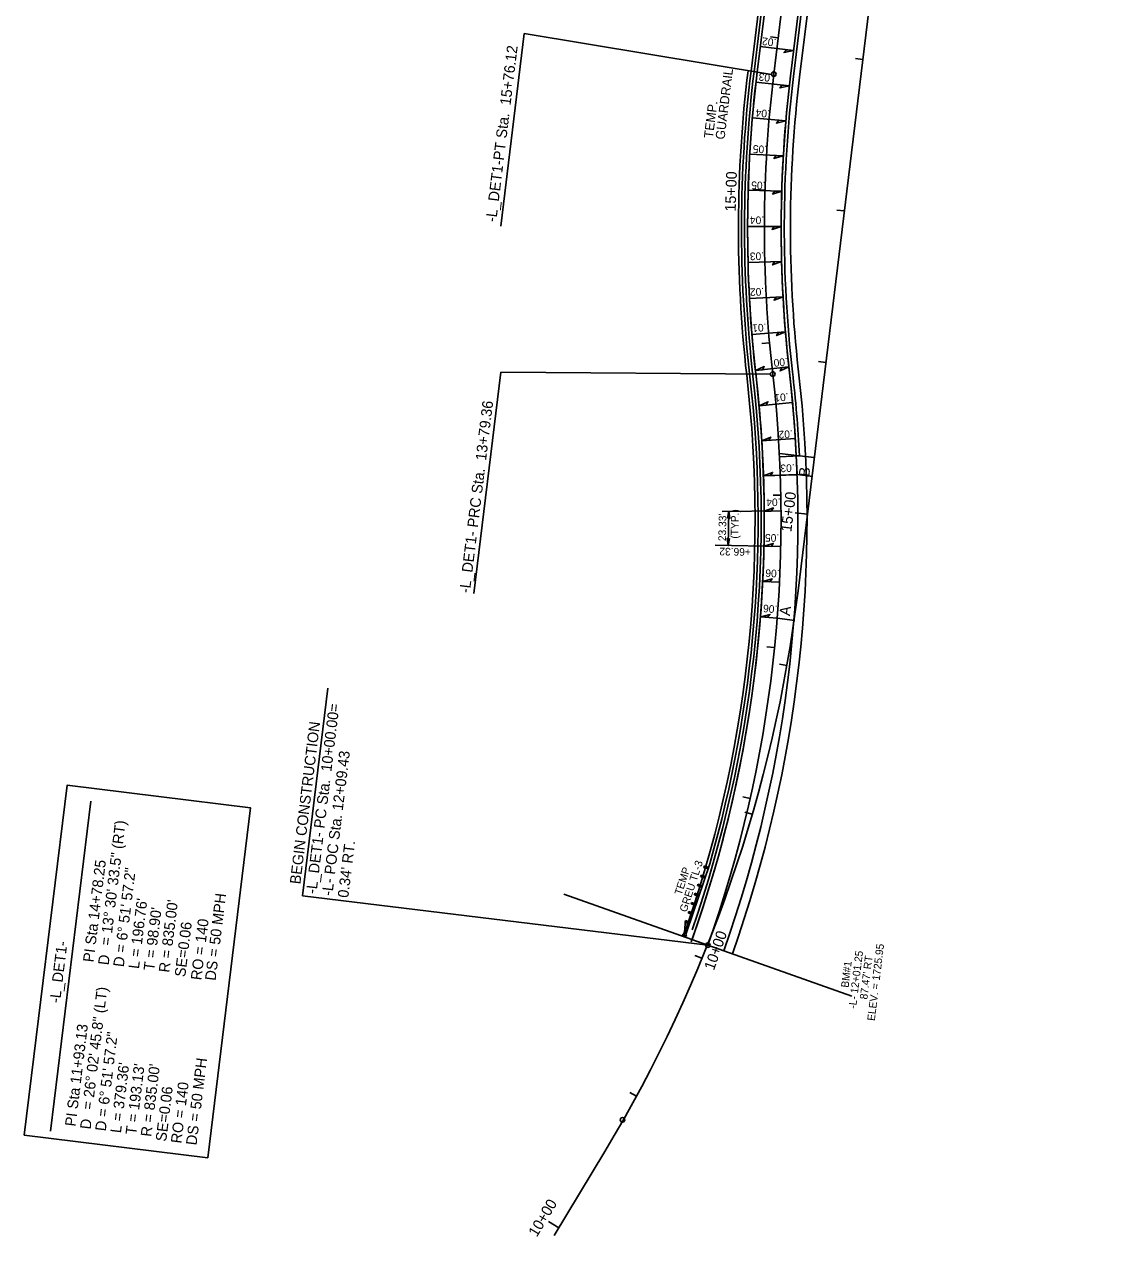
# Model space of a CAD drawing. Extents: x 473658 to 481584, y 489119 to 506230.
# Drawn here: x 480694 to 481402, y 489119 to 489912 of the extents above; entities that cross this region are included whole.
import ezdxf

# ---------------------------------------------------------------- set-up
doc = ezdxf.new("R2010")
doc.units = 0
for name, color, linetype in [('Default', 7, 'Continuous'), ('Exist Structure Minor Culvert Topo', 7, 'Continuous'), ('Prop EOT', 7, 'Continuous'), ('Prop Grid Mask', 7, 'Continuous'), ('Prop Guardrail', 7, 'Continuous'), ('Prop Guardrail Anchor Unit CELL', 7, 'Continuous'), ('Prop Horizontal Alignment', 7, 'Continuous'), ('Prop Horizontal Alignment Curve and Spiral Data', 7, 'Continuous'), ('Prop Horizontal Alignment Station Label', 7, 'Continuous'), ('Prop Horizontal Alignment Tick Label', 7, 'Continuous'), ('Prop Horizontal Alignment Tick Large', 7, 'Continuous'), ('Prop Horizontal Alignment Tick Small', 7, 'Continuous'), ('Prop Paved Shoulder', 7, 'Continuous'), ('Prop Superelevation  Arrow CELL', 7, 'Continuous'), ('Prop Superelevation Label', 7, 'Continuous'), ('Scratch_Level_2', 7, 'Continuous'), ('Scratch_Level_3', 7, 'Continuous'), ('Scratch_Level_4', 7, 'Continuous'), ('Scratch_Level_5', 7, 'Continuous'), ('Scratch_Level_6', 7, 'Continuous'), ('Scratch_Level_9', 7, 'Continuous'), ('Sheet Profile Grid Major CELL', 7, 'Continuous')]:
    doc.layers.add(name, color=color, linetype=linetype)

msp = doc.modelspace()

# ---------------------------------------------------------------- linework, layer by layer
at = {"layer": 'Prop EOT'}
for p, q in [((481195.32, 489878.54), (481333.26, 491007.97)), ((481173.48, 489881.21), (481217.26, 490239.65))]:
    msp.add_line(p, q, dxfattribs=at)
for centre, radius, start, end in [((482013.24, 489778.65), 846, 173.03651, 186.54581), ((482013.24, 489778.65), 824, 173.03651, 186.54581), ((480354.13, 489588.27), 824, 340.39021, 6.54581), ((480354.13, 489588.27), 846, 1.98866, 6.54581)]:
    msp.add_arc(centre, radius, start, end, dxfattribs=at)
at = {"layer": 'Prop Grid Mask'}
msp.add_lwpolyline([(480693.88, 489185.04), (480721.87, 489414.21), (480841.92, 489399.55), (480813.93, 489170.38)], close=True, dxfattribs=at)
at = {"layer": 'Prop Guardrail'}
msp.add_line((481207.7, 490194.38), (481169.51, 489881.7), dxfattribs=at)
for centre, radius, start, end in [((482013.24, 489778.65), 850, 173.03651, 186.54581), ((480354.13, 489588.27), 820, 344.04145, 6.54581)]:
    msp.add_arc(centre, radius, start, end, dxfattribs=at)
at = {"layer": 'Prop Guardrail Anchor Unit CELL'}
for p, q in [((481142.53, 489362.82), (481127.46, 489318.56)), ((481136.79, 489355.43), (481136.46, 489354.48)), ((481136.46, 489354.48), (481138.23, 489354.94)), ((481139.35, 489353.5), (481136.46, 489354.48)), ((481139.68, 489354.44), (481136.79, 489355.43)), ((481137.91, 489353.99), (481136.79, 489355.43)), ((481138.23, 489354.94), (481137.91, 489353.99)), ((481138.23, 489354.94), (481139.35, 489353.5)), ((481138.87, 489361.38), (481138.54, 489360.43)), ((481138.54, 489360.43), (481140.29, 489360.89)), ((481141.38, 489359.46), (481138.54, 489360.43)), ((481141.71, 489360.41), (481138.87, 489361.38)), ((481139.96, 489359.95), (481138.87, 489361.38)), ((481140.29, 489360.89), (481139.96, 489359.95)), ((481139.96, 489359.95), (481141.71, 489360.41)), ((481141.38, 489359.46), (481139.96, 489359.95)), ((481140.29, 489360.89), (481141.38, 489359.46)), ((481141.71, 489360.41), (481141.38, 489359.46)), ((481134.76, 489349.46), (481134.44, 489348.51)), ((481134.44, 489348.51), (481136.2, 489348.97)), ((481137.32, 489347.53), (481134.44, 489348.51)), ((481137.65, 489348.48), (481134.76, 489349.46)), ((481135.88, 489348.02), (481134.76, 489349.46)), ((481136.2, 489348.97), (481135.88, 489348.02)), ((481137.65, 489348.48), (481135.88, 489348.02)), ((481136.2, 489348.97), (481137.32, 489347.53)), ((481139.68, 489354.44), (481137.91, 489353.99)), ((481132.74, 489343.49), (481132.42, 489342.55)), ((481132.42, 489342.55), (481134.18, 489343)), ((481135.29, 489341.57), (481132.42, 489342.55)), ((481135.62, 489342.51), (481132.74, 489343.49)), ((481133.86, 489342.06), (481132.74, 489343.49)), ((481134.18, 489343), (481133.86, 489342.06)), ((481135.62, 489342.51), (481133.86, 489342.06)), ((481134.18, 489343), (481135.29, 489341.57)), ((481135.62, 489342.51), (481135.29, 489341.57)), ((481128.72, 489331.55), (481128.4, 489330.6)), ((481128.4, 489330.6), (481130.14, 489331.07)), ((481131.56, 489330.58), (481128.72, 489331.55)), ((481129.81, 489330.12), (481128.72, 489331.55)), ((481130.14, 489331.07), (481129.81, 489330.12)), ((481130.14, 489331.07), (481131.23, 489329.64)), ((481130.62, 489337.56), (481130.29, 489336.61)), ((481130.29, 489336.61), (481132.1, 489337.05)), ((481133.26, 489335.6), (481130.29, 489336.61)), ((481133.59, 489336.55), (481130.62, 489337.56)), ((481131.78, 489336.11), (481130.62, 489337.56)), ((481132.1, 489337.05), (481131.78, 489336.11)), ((481133.59, 489336.55), (481131.78, 489336.11)), ((481132.1, 489337.05), (481133.26, 489335.6)), ((481126.3, 489324.66), (481126.21, 489319.51)), ((481126.63, 489325.6), (481126.3, 489324.66)), ((481126.3, 489324.66), (481128.08, 489325.11)), ((481129.2, 489323.67), (481126.3, 489324.66)), ((481129.53, 489324.62), (481126.63, 489325.6)), ((481127.75, 489324.16), (481126.63, 489325.6)), ((481127.75, 489324.16), (481127.63, 489319.03)), ((481128.08, 489325.11), (481127.75, 489324.16)), ((481129.53, 489324.62), (481127.75, 489324.16)), ((481128.08, 489325.11), (481129.2, 489323.67)), ((481131.23, 489329.64), (481128.4, 489330.6)), ((481131.56, 489330.58), (481129.81, 489330.12)), ((481124.42, 489316.12), (481125.6, 489316.98)), ((481127.22, 489315.22), (481124.42, 489316.12)), ((481125.6, 489316.98), (481126.22, 489318.93)), ((481126.21, 489319.51), (481125.88, 489318.57)), ((481125.88, 489318.57), (481127.63, 489319.03)), ((481127.3, 489318.08), (481125.88, 489318.57)), ((481126.21, 489319.51), (481126.04, 489319.04)), ((481127.63, 489319.03), (481126.21, 489319.51)), ((481127.3, 489318.08), (481126.21, 489319.51)), ((481126.22, 489318.93), (481126.8, 489318.74)), ((481127.38, 489318.55), (481126.76, 489316.6)), ((481126.76, 489316.6), (481127.22, 489315.22)), ((481126.8, 489318.74), (481127.38, 489318.55))]:
    msp.add_line(p, q, dxfattribs=at)
at = {"layer": 'Prop Horizontal Alignment'}
for p, q in [((481200.24, 489541.46), (481402.27, 491195.58)), ((481184.4, 489879.88), (481322.35, 491009.3)), ((481040.66, 489119.43), (481073.76, 489174.39))]:
    msp.add_line(p, q, dxfattribs=at)
for centre, radius, start, end in [((482013.24, 489778.65), 835, 173.03651, 186.54581), ((480354.13, 489588.27), 835, 340.49976, 6.54581), ((480277.1, 489654.21), 930, 328.94039, 353.03651)]:
    msp.add_arc(centre, radius, start, end, dxfattribs=at)
at = {"layer": 'Prop Horizontal Alignment Curve and Spiral Data'}
msp.add_line((480710.96, 489187.73), (480737.35, 489403.9), dxfattribs=at)
at = {"layer": 'Prop Horizontal Alignment Station Label'}
for p, q in [((481005.7, 489780.23), (481021.12, 489906.51)), ((481182.91, 489879.7), (481021.12, 489906.51)), ((480988.08, 489539.7), (481005.8, 489684.72)), ((481182.19, 489683.29), (481005.8, 489684.72)), ((480876.03, 489341.93), (480892.63, 489477.88)), ((481141.23, 489309.54), (480876.03, 489341.93))]:
    msp.add_line(p, q, dxfattribs=at)
for centre in [(481184.4, 489879.88), (481183.68, 489683.46), (481141.23, 489309.54), (481085.34, 489195.19), (481085.34, 489195.19)]:
    msp.add_circle(centre, 1.5, dxfattribs=at)
at = {"layer": 'Prop Horizontal Alignment Tick Large'}
for p, q in [((481178.62, 489803.96), (481170.63, 489804.21)), ((481206.38, 489591.73), (481198.43, 489592.7)), ((481141.23, 489309.54), (481133.69, 489312.21)), ((481043.72, 489124.51), (481036.86, 489128.63))]:
    msp.add_line(p, q, dxfattribs=at)
at = {"layer": 'Prop Horizontal Alignment Tick Small'}
for p, q in [((481187.3, 489903.59), (481182.33, 489904.19)), ((481242.75, 489889.52), (481237.78, 489890.12)), ((481230.62, 489790.25), (481225.66, 489790.86)), ((481181.58, 489704.01), (481176.6, 489703.56)), ((481218.5, 489690.99), (481213.54, 489691.6)), ((481188.97, 489604.26), (481183.98, 489604.17)), ((481184.9, 489504.34), (481179.92, 489504.85)), ((481192.95, 489492.65), (481188.03, 489493.52)), ((481168.91, 489405.63), (481164.03, 489406.72)), ((481170.33, 489395.29), (481165.52, 489396.68)), ((481137.38, 489300.93), (481132.76, 489302.83)), ((481094.5, 489210.64), (481090.1, 489213.03))]:
    msp.add_line(p, q, dxfattribs=at)
at = {"layer": 'Prop Paved Shoulder'}
for p, q in [((481171.5, 489881.45), (481216, 490245.85)), ((481197.3, 489878.3), (481209.6, 489978.94))]:
    msp.add_line(p, q, dxfattribs=at)
for centre, radius, start, end in [((482013.24, 489778.65), 848, 173.03651, 186.54581), ((482013.24, 489778.65), 822, 173.03651, 186.54581), ((480354.13, 489588.27), 822, 340.91826, 6.54581), ((480354.13, 489588.27), 848, 2.81645, 6.54581)]:
    msp.add_arc(centre, radius, start, end, dxfattribs=at)
at = {"layer": 'Prop Superelevation  Arrow CELL'}
msp.add_line((481154.54, 489571.21), (481154.95, 489593.59), dxfattribs=at)
for points in [[(481197.36, 489895.25), (481191.16, 489893.99), (481192.77, 489895.81)], [(481194.57, 489872.17), (481188.38, 489870.86), (481189.97, 489872.69)], [(481192.27, 489849.24), (481186.12, 489847.77), (481187.66, 489849.64)], [(481190.62, 489826.27), (481184.51, 489824.62), (481186, 489826.54)], [(481189.61, 489803.17), (481183.55, 489801.35), (481184.99, 489803.3)], [(481189.25, 489780.13), (481183.24, 489778.14), (481184.62, 489780.14)], [(481189.52, 489757.1), (481183.58, 489754.94), (481184.9, 489756.98)], [(481190.45, 489734.08), (481184.56, 489731.76), (481185.83, 489733.83)], [(481192.01, 489711.1), (481186.2, 489708.61), (481187.4, 489710.72)], [(481172.36, 489685.75), (481178.1, 489688.4), (481176.95, 489686.26)], [(481194.22, 489688.17), (481188.48, 489685.52), (481189.63, 489687.66)], [(481174.75, 489662.75), (481180.54, 489665.3), (481179.36, 489663.18)], [(481176.52, 489639.78), (481182.38, 489642.15), (481181.13, 489640.07)], [(481177.63, 489616.77), (481183.55, 489619.01), (481182.26, 489616.96)], [(481154.09, 489589.1), (481154.95, 489593.59), (481155.67, 489589.05), (481154.88, 489589.64)], [(481178.11, 489593.74), (481184.1, 489595.78), (481182.74, 489593.77)], [(481155.39, 489575.69), (481154.54, 489571.21), (481153.82, 489575.75), (481154.61, 489575.16)], [(481177.94, 489570.71), (481183.98, 489572.58), (481182.56, 489570.61)], [(481177.13, 489547.69), (481183.22, 489549.39), (481181.75, 489547.46)], [(481175.66, 489524.58), (481181.8, 489526.11), (481180.27, 489524.22)]]:
    msp.add_lwpolyline(points, close=True, dxfattribs=at)
at = {"layer": 'Prop Superelevation Label'}
for p, q in [((481175.52, 489897.91), (481197.36, 489895.25)), ((481172.71, 489874.66), (481194.57, 489872.17)), ((481170.35, 489851.13), (481192.27, 489849.24)), ((481168.65, 489827.54), (481190.62, 489826.27)), ((481167.62, 489803.82), (481189.61, 489803.17)), ((481167.24, 489780.17), (481189.24, 489780.13)), ((481167.53, 489756.52), (481189.52, 489757.1)), ((481168.48, 489732.89), (481190.45, 489734.08)), ((481170.09, 489709.3), (481192.01, 489711.1)), ((481172.36, 489685.75), (481194.22, 489688.17)), ((481174.75, 489662.75), (481196.66, 489664.74)), ((481176.52, 489639.78), (481198.47, 489641.16)), ((481177.63, 489616.77), (481199.62, 489617.53)), ((481150.64, 489593.56), (481189.11, 489593.82)), ((481145.98, 489571.39), (481188.94, 489570.47)), ((481188.1, 489547.15), (481177.13, 489547.69)), ((481186.62, 489523.73), (481175.66, 489524.58))]:
    msp.add_line(p, q, dxfattribs=at)
at = {"layer": 'Scratch_Level_2'}
for centre, radius, start, end in [((482014.25, 489778.63), 853, 173.03651, 186.44009), ((482014.25, 489778.63), 847, 173.03651, 186.44009), ((482014.25, 489778.63), 825, 173.03651, 186.44009), ((482014.25, 489778.63), 819, 173.03651, 186.44009), ((480354.13, 489588.27), 818, 340.49976, 6.64279), ((480354.13, 489588.27), 824, 340.49976, 6.64279), ((480354.13, 489588.27), 846, 340.49976, 6.64279), ((480354.13, 489588.27), 852, 340.49976, 6.64279)]:
    msp.add_arc(centre, radius, start, end, dxfattribs=at)
at = {"layer": 'Scratch_Level_3'}
for p, q in [((481199.62, 489617.63), (481177.63, 489616.86)), ((481186.63, 489523.73), (481198.1, 489522.04))]:
    msp.add_line(p, q, dxfattribs=at)
at = {"layer": 'Scratch_Level_4'}
msp.add_arc((480354.13, 489588.27), 835, 340.49976, 6.54581, dxfattribs=at)
at = {"layer": 'Scratch_Level_5'}
for p, q in [((481201.27, 489877.82), (481339.22, 491007.24)), ((481199.62, 489617.63), (481209.91, 489616.37)), ((481186.63, 489523.73), (481198.1, 489522.04))]:
    msp.add_line(p, q, dxfattribs=at)
for centre, radius, end in [((482014.25, 489778.63), 853, 186.44009), ((482013.24, 489778.65), 835, 186.54581)]:
    msp.add_arc(centre, radius, 173.03651, end, dxfattribs=at)
at = {"layer": 'Scratch_Level_6'}
for p, q in [((481188.01, 489631.54), (481210.9, 489628.74)), ((481201.1, 489629.94), (481188.12, 489629.3))]:
    msp.add_line(p, q, dxfattribs=at)
at = {"layer": 'Scratch_Level_9'}
msp.add_line((481046.97, 489342.92), (481235.5, 489276.16), dxfattribs=at)

# ---------------------------------------------------------------- texts
at = {"layer": 'Default'}
for s, p in [('ELEV. = 1725.95 ', (481250.45, 489259.75)), ('-L- 12+01.25', (481238.22, 489267.74)), ("87.47' RT", (481245.56, 489273.79)), ('BM#1', (481233.3, 489281.49))]:
    msp.add_text(s, height=5, rotation=83.03651, dxfattribs=at).set_placement(p)
at = {"layer": 'Exist Structure Minor Culvert Topo'}
for s, p in [('GREU TL-3', (481127.29, 489330.78)), ('TEMP', (481124.02, 489341.95))]:
    msp.add_text(s, height=5, rotation=72.04608, dxfattribs=at).set_placement(p)
at = {"layer": 'Prop Horizontal Alignment Curve and Spiral Data'}
for s, rotation, p in [('= 13%%d 30\' 33.5" (RT)', 83.03651, (480750.33, 489308.98)), ('PI Sta 14+78.25', 83.03651, (480739.22, 489298.07)), ('D = 6%%d 51\' 57.2"', 83.03651, (480758.99, 489294.98)), ("L = 196.76'", 83.03651, (480768.92, 489293.77)), ("R = 835.00'", 83.03651, (480788.77, 489291.34)), ('DS = 50 MPH', 83.03983, (480819.05, 489286.02)), ("T = 98.90'", 83.03651, (480778.84, 489292.55)), ('SE=0.06', 83.03983, (480799.2, 489288.44)), ('RO = 140', 83.03983, (480809.72, 489286.35)), ('-L_DET1-', 83.03983, (480717.28, 489271.42)), ('D', 83.03651, (480749.07, 489296.19)), ('= 26%%d 02\' 45.8" (LT)', 83.03651, (480738.53, 489201.48)), ('PI Sta 11+93.13', 83.03651, (480727.42, 489190.57)), ('D = 6%%d 51\' 57.2"', 83.03651, (480747.19, 489187.48)), ('DS = 50 MPH', 83.03983, (480806.59, 489178.25)), ("L = 379.36'", 83.03651, (480757.12, 489186.26)), ("T = 193.13'", 83.03651, (480767.04, 489185.05)), ("R = 835.00'", 83.03651, (480776.97, 489183.84)), ('RO = 140', 83.03983, (480796.67, 489179.46)), ('SE=0.06', 83.03983, (480786.74, 489180.68)), ('D', 83.03651, (480737.27, 489188.69))]:
    msp.add_text(s, height=7, rotation=rotation, dxfattribs=at).set_placement(p)
at = {"layer": 'Prop Horizontal Alignment Station Label'}
for s, p in [('-L_DET1-PT Sta.  15+76.12', (481002.74, 489782.75)), ('-L_DET1- PRC Sta.  13+79.36', (480985.45, 489539.8)), ('-L_DET1- PC Sta.  10+00.00=', (480885.05, 489342.82)), ('BEGIN CONSTRUCTION', (480874.54, 489349.18)), ('-L- POC Sta. 12+09.43', (480895.47, 489341.55)), ("0.34' RT. ", (480905.89, 489340.27))]:
    msp.add_text(s, height=7, rotation=83.03651, dxfattribs=at).set_placement(p)
at = {"layer": 'Prop Horizontal Alignment Tick Label'}
for s, rotation, p in [('15+00', 88.26248, (481159.44, 489789.78)), ('15+00', 83.03651, (481195.85, 489579.8)), ('10+00', 70.49976, (481145.16, 489292.59)), ('10+00', 58.94039, (481029.3, 489118.01))]:
    msp.add_text(s, height=7, rotation=rotation, dxfattribs=at).set_placement(p)
at = {"layer": 'Prop Superelevation  Arrow CELL'}
for s, rotation, p in [('.02', 173.03651, (481186.29, 489902.8)), ('.03', 173.48314, (481184.06, 489879.56)), ('.04', 175.08495, (481182.03, 489856.23)), ('.05', 176.68676, (481180.1, 489832.89)), ('.05', 178.29475, (481179, 489809.35)), ('.04', 179.89656, (481178.06, 489786.65)), ('.03', 181.49836, (481177.94, 489763.24)), ('.02', 183.10017, (481177.95, 489739.96)), ('.01', 184.70198, (481179.34, 489716.6)), ('.00', 186.30379, (481193.26, 489694.14)), ('.01', 185.18602, (481193.81, 489671.07)), ('.02', 183.58421, (481196.62, 489646.77)), ('.03', 181.9824, (481197.92, 489624.5)), ('(TYP.)', 88.98084, (481161.14, 489575.64)), ("23.33'", 88.98084, (481153.06, 489574.01)), ('+66.32', 178.98084, (481169.44, 489569.41))]:
    msp.add_text(s, height=5, rotation=rotation, dxfattribs=at).set_placement(p)
at = {"layer": 'Prop Superelevation Label'}
for s, rotation, p in [('.04', 180.3806, (481188.74, 489602.02)), ('.05', 178.77879, (481187.99, 489578.58)), ('.06', 177.17698, (481188.29, 489555.21)), ('.06', 175.56693, (481186.84, 489531.83))]:
    msp.add_text(s, height=5, rotation=rotation, dxfattribs=at).set_placement(p)
at = {"layer": 'Scratch_Level_3'}
for s, p in [('B', (481207.56, 489615.94)), ('A', (481194.88, 489524.9))]:
    msp.add_text(s, height=7, rotation=83.03651, dxfattribs=at).set_placement(p)
at = {"layer": 'Sheet Profile Grid Major CELL'}
for s, p in [('GUARDRAIL', (481152.09, 489836.75)), ('TEMP.', (481144.54, 489837.67))]:
    msp.add_text(s, height=6, rotation=83.03651, dxfattribs=at).set_placement(p)

doc.saveas('drawing.dxf')
